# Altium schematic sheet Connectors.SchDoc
size A; SheetNumber: 1; SheetTotal: 1
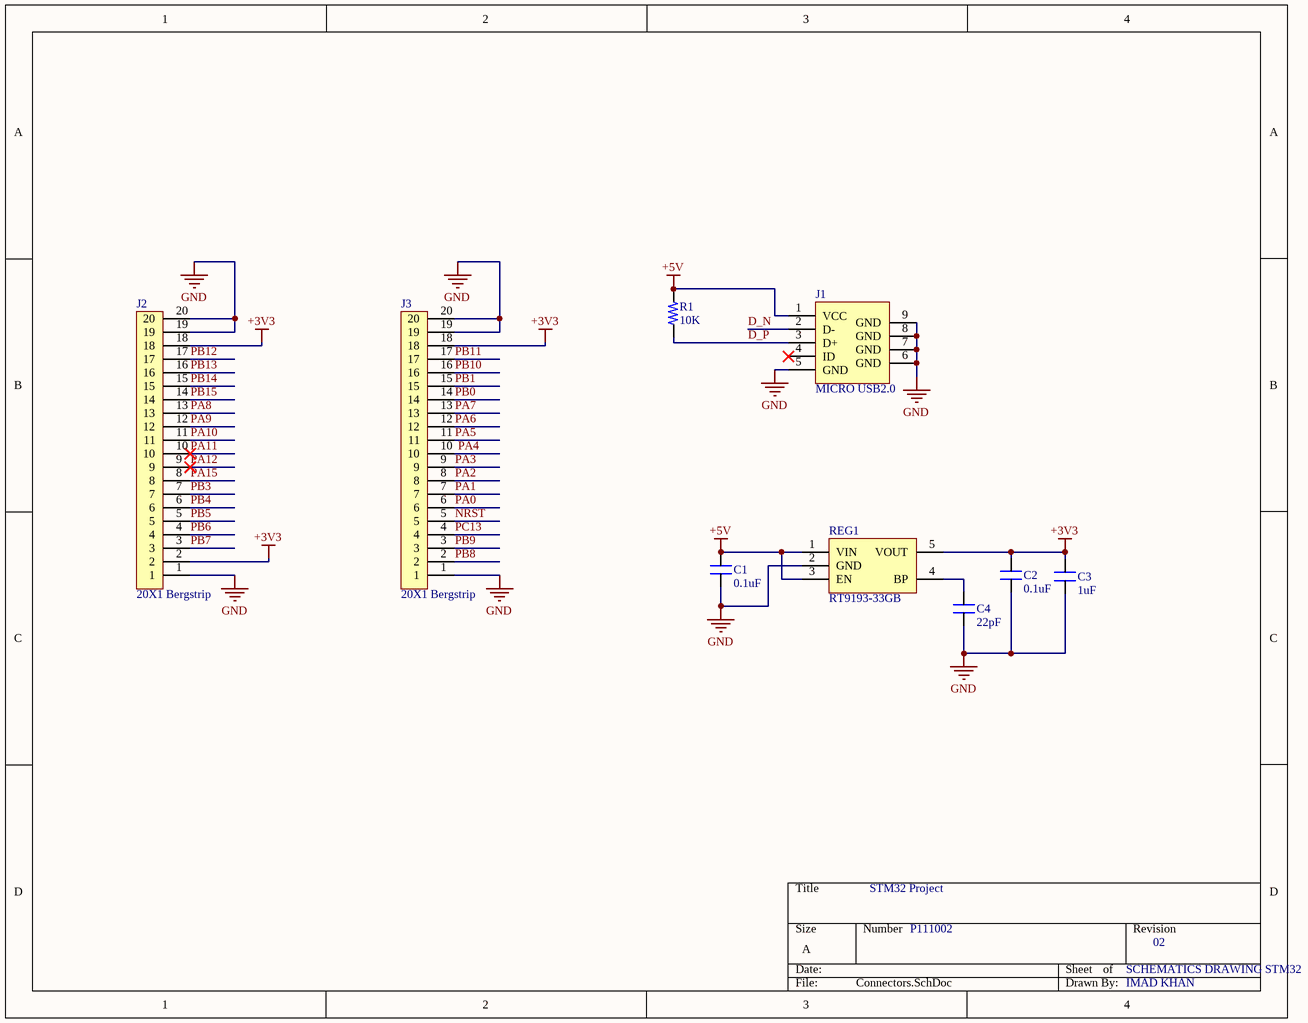
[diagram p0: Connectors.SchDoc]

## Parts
C1  0.1uF  [CAP_0805]
C2  0.1uF  [CAP_0805]
C3  1uF  [CAP_0805]
C4  22pF  [CAP_0805]
J1  MICRO USB2.0  [CON_10118192-0001LF_SMD]
J2  20X1 Bergstrip  [CON20_100_40D72_TH_ST]
J3  20X1 Bergstrip  [CON20_100_40D72_TH_ST]
R1  10K  [RES_0805]
REG1  RT9193-33GB  [SOT23-5]

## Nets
+3V3: C2.2 C3.2 J2.2 J2.18 J3.18 REG1.5(VOUT)
+5V: C1.2 J1.1(VCC) R1.2 REG1.1(VIN) REG1.3(EN)
GND: C1.1 C2.1 C3.1 C4.1 J1.5(GND) J1.6(GND) J1.7(GND) J1.8(GND) J1.9(GND) J2.1 J2.19 J2.20 J3.1 J3.19 J3.20 REG1.2(GND)
D_N: J1.2(D-)
D_P: J1.3(D+) R1.1
NRST: J3.5
PA0: J3.6
PA1: J3.7
PA2: J3.8
PA3: J3.9
PA4: J3.10
PA5: J3.11
PA6: J3.12
PA7: J3.13
PA8: J2.13
PA9: J2.12
PA10: J2.11
PA11: J2.10
PA12: J2.9
PA15: J2.8
PB0: J3.14
PB1: J3.15
PB3: J2.7
PB4: J2.6
PB5: J2.5
PB6: J2.4
PB7: J2.3
PB8: J3.2
PB9: J3.3
PB10: J3.16
PB11: J3.17
PB12: J2.17
PB13: J2.16
PB14: J2.15
PB15: J2.14
PC13: J3.4
NetC4_2: C4.2 REG1.4(BP)

Not connected (* = marked no-connect by the designer): J1 4(ID)*

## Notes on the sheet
- STM32 Project
- P111002
- SCHEMATICS DRAWING STM32
- 02
- IMAD KHAN

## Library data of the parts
C1 C2 = CAP_0.1uF-50V-5%-0805: 0.1µF ±5% 50V Ceramic Capacitor X7R 0805 (2012 Metric); Manufacturer: KEMET; Manufacturing Part Number: C0805C104J5RACTU
C3 = CAP_1uF-50V-5%-0805: 1µF ±5% 50V Ceramic Capacitor X7R 0805 (2012 Metric); Manufacturer: Yageo; Manufacturing Part Number: CC0805JKX7R9BB105
C4 = CAP_22pF-50V-5%-0805: 22pF ±5% 50V Ceramic Capacitor C0G, NP0 0805 (2012 Metric); Manufacturer: KEMET; Manufacturer Part Number: C0805C220J5GACTU
J1 = CON-USB_10118192-0002LF-SMD: USB - micro B USB 2.0 Receptacle Connector 5 Position Surface Mount, Right Angle; Manufacturer: Amphenol ICC (FCI)
J2 J3 = CON-BS-PLG_20X1-100-TH-ST: 20 pin, 1 row, 2.54mm pitch bergstrip; Manufacturer: NA
R1 = RES_10K-0.125W-1%-0805: 10 kOhms ±1% 0.125W, 1/8W Chip Resistor 0805 (2012 Metric) Moisture Resistant Thick Film; Manufacturer: Yageo; Manufacturing Part Number: RC0805FR-0710KL
REG1 = REG_3.3V-5.5V-0.3A-SOT-23-5: Linear Voltage Regulator IC 1 Output 300mA SOT-23-5; Manufacturer: Richtek USA Inc.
